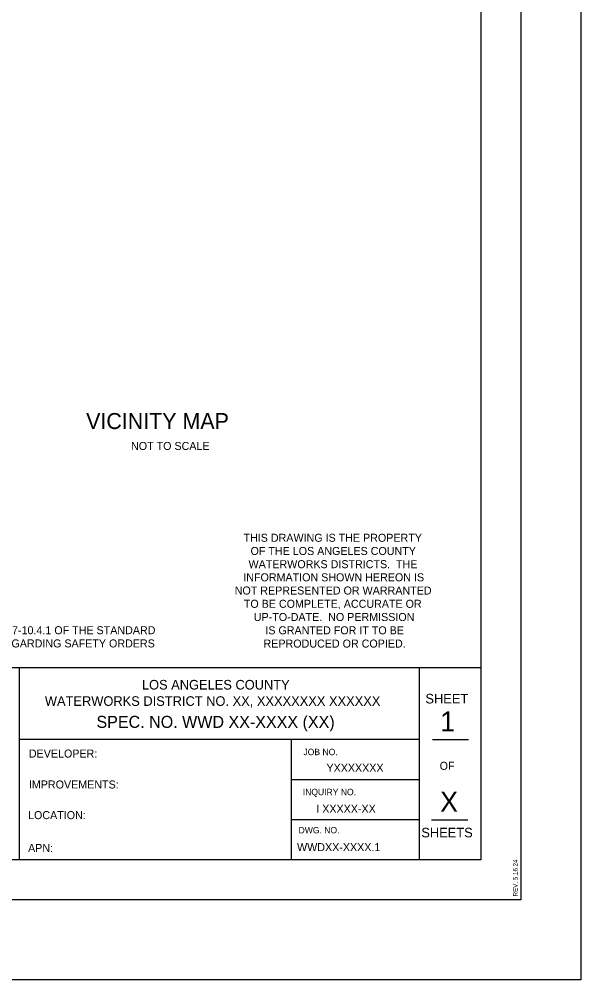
# Model space of a CAD drawing. Extents: x 837 to 1117, y 1316 to 1424.
# Drawn here: x 870.76 to 877.77, y 1398.24 to 1410.24 of the extents above; entities that cross this region are included whole.
import ezdxf

# ---------------------------------------------------------------- set-up
doc = ezdxf.new("R2010")
doc.units = 0
for name, color, linetype in [('0 (Construction)', 7, 'Continuous'), ('BASEMAP', 7, 'Continuous'), ('CONSNOTE', 7, 'Continuous'), ('LLINES', 7, 'Continuous'), ('TEXT', 7, 'Continuous')]:
    doc.layers.add(name, color=color, linetype=linetype)

msp = doc.modelspace()

# ---------------------------------------------------------------- linework, layer by layer
at = {"layer": '0 (Construction)'}
msp.add_lwpolyline([(841.77, 1422.24), (877.77, 1422.24), (877.77, 1398.24), (841.77, 1398.24)], close=True, dxfattribs=at)
at = {"layer": 'BASEMAP'}
for p, q in [((877.02, 1421.24), (877.02, 1399.24)), ((876.52, 1420.74), (876.52, 1399.74)), ((875.752, 1401.24), (870.755, 1401.24)), ((875.752, 1400.74), (874.152, 1400.74)), ((875.752, 1400.24), (874.152, 1400.24)), ((876.52, 1399.74), (843.52, 1399.74)), ((877.02, 1399.24), (843.02, 1399.24))]:
    msp.add_line(p, q, dxfattribs=at)
for points in [[(867.255, 1402.14), (876.52, 1402.14)], [(870.755, 1402.14), (870.755, 1399.74)], [(875.752, 1402.14), (875.752, 1399.74)], [(874.152, 1401.24), (874.152, 1399.74)]]:
    msp.add_lwpolyline(points, dxfattribs=at)
at = {"layer": 'LLINES'}
for p, q in [((875.919, 1401.242), (876.369, 1401.242)), ((875.907, 1400.238), (876.358, 1400.238))]:
    msp.add_line(p, q, dxfattribs=at)

# ---------------------------------------------------------------- texts
at = {"layer": 'CONSNOTE'}
msp.add_text('VICINITY MAP', height=0.2, dxfattribs=at).set_placement((871.591, 1405.12))
at = {"layer": 'LLINES'}
for s, height, p in [('REFER TO SECTION 7-10.4.1 OF THE STANDARD ', 0.1, (869.321, 1402.557)), ('SPECIFICATIONS REGARDING SAFETY ORDERS', 0.1, (869.321, 1402.392)), ('LOS ANGELES COUNTY', 0.12, (872.288, 1401.866)), ('WATERWORKS DISTRICT NO. XX, XXXXXXXX XXXXXX', 0.12, (871.076, 1401.662)), ('SHEET', 0.12, (875.829, 1401.692)), ('SPEC. NO. WWD XX-XXXX (XX)', 0.15, (871.72, 1401.387)), ('1', 0.25, (876.013, 1401.342)), ('JOB NO.', 0.08, (874.305, 1401.046)), ('DEVELOPER: ', 0.1, (870.876, 1401.016)), ('OF', 0.1, (876.007, 1400.863)), ('IMPROVEMENTS:', 0.1, (870.876, 1400.63)), ('INQUIRY NO.', 0.08, (874.297, 1400.546)), ('X', 0.25, (876.013, 1400.339)), ('LOCATION: ', 0.1, (870.866, 1400.247)), ('DWG. NO.', 0.08, (874.245, 1400.069)), ('SHEETS', 0.12, (875.778, 1400.019)), ('APN:', 0.1, (870.866, 1399.836))]:
    msp.add_text(s, height=height, dxfattribs=at).set_placement(p)
msp.add_text('REV. 5.16.24', height=0.05636, rotation=90, dxfattribs=at).set_placement((876.981, 1399.281))
at = {"layer": 'TEXT'}
for s, p in [('NOT TO SCALE', (872.152, 1404.859)), ('THIS DRAWING IS THE PROPERTY', (873.557, 1403.712)), ('OF THE LOS ANGELES COUNTY', (873.645, 1403.547)), ('WATERWORKS DISTRICTS.  THE', (873.62, 1403.382)), ('INFORMATION SHOWN HEREON IS', (873.554, 1403.218)), ('NOT REPRESENTED OR WARRANTED', (873.447, 1403.053)), ('TO BE COMPLETE, ACCURATE OR', (873.561, 1402.887)), ('UP-TO-DATE.  NO PERMISSION', (873.686, 1402.722)), ('IS GRANTED FOR IT TO BE', (873.83, 1402.556)), ('REPRODUCED OR COPIED.', (873.807, 1402.39)), ('YXXXXXXX', (874.593, 1400.838)), ('I XXXXX-XX', (874.466, 1400.327)), ('WWDXX-XXXX.1', (874.226, 1399.847))]:
    msp.add_text(s, height=0.1, dxfattribs=at).set_placement(p)

doc.saveas('drawing.dxf')
